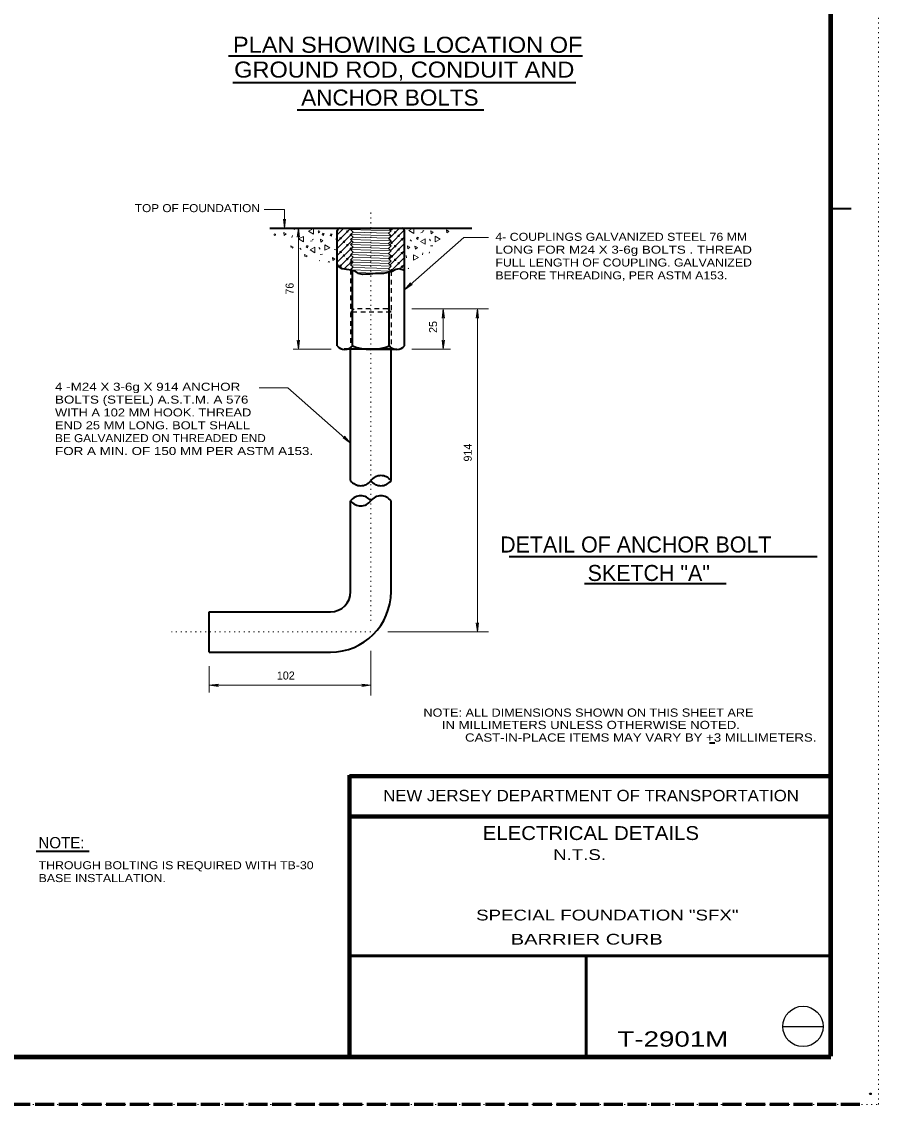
# Model space of a CAD drawing. Extents: x 312583 to 312854, y 144419 to 144597.
# Drawn here: x 312772.2 to 312853.5, y 144418.6 to 144521.4 of the extents above; entities that cross this region are included whole.
import ezdxf
from ezdxf.enums import TextEntityAlignment as Align

# ---------------------------------------------------------------- set-up
doc = ezdxf.new("R2010")
doc.units = 0
doc.header["$LTSCALE"] = 0.3
doc.header["$PDMODE"] = 32
doc.header["$PDSIZE"] = 0.15
for name, pattern in [('DOTTED', [1.5, 0.3, -1.2]), ('LONG_DASHED', [7.5, 6, -1.5]), ('SHORT_DASHED', [2.7, 1.5, -1.2])]:
    doc.linetypes.add(name, pattern=pattern)
for name, color, linetype, lineweight in [('1', 7, 'Continuous', 25), ('10', 7, 'Continuous', 25), ('2', 7, 'Continuous', 13), ('62', 7, 'DOTTED', 13), ('63', 7, 'LONG_DASHED', 60)]:
    doc.layers.add(name, color=color, linetype=linetype, lineweight=lineweight)
doc.layers.add('50', color=7, linetype='Continuous')

msp = doc.modelspace()

# ---------------------------------------------------------------- linework, layer by layer
at = {"layer": '1', "lineweight": 158}
for p, q in [((312849, 144423.1446), (312849, 144585.0846)), ((312616.5, 144423.0846), (312849, 144423.0846))]:
    msp.add_line(p, q, dxfattribs=at)
at = {"layer": '1', "linetype": 'DOTTED', "lineweight": 13}
for p, q in [((312805.3246, 144503.2268), (312805.3246, 144464.4028)), ((312805.3246, 144463.4214), (312786.4032, 144463.4214))]:
    msp.add_line(p, q, dxfattribs=at)
at = {"layer": '1', "lineweight": 35}
for p, q in [((312849, 144503.6216), (312850.932, 144503.6216)), ((312837.4764, 144452.901), (312837.9863, 144452.901))]:
    msp.add_line(p, q, dxfattribs=at)
at = {"layer": '1', "lineweight": 40}
for p, q in [((312802.1352, 144490.5691), (312802.1352, 144501.5171)), ((312808.2839, 144501.7548), (312814.9156, 144501.7548)), ((312808.5216, 144490.5691), (312808.5216, 144501.5171)), ((312803.5689, 144490.5691), (312803.5689, 144497.7221)), ((312807.0802, 144490.5691), (312807.0802, 144497.5764)), ((312807.2412, 144490.2548), (312802.8022, 144490.2548)), ((312805.3246, 144490.2548), (312802.8559, 144490.2548)), ((312803.4079, 144477.7888), (312803.4079, 144490.2548)), ((312805.3246, 144490.2548), (312807.8009, 144490.2548)), ((312807.2412, 144477.7888), (312807.2412, 144490.2548)), ((312803.4079, 144467.2548), (312803.4079, 144475.8721)), ((312807.2412, 144467.2548), (312807.2412, 144475.8721)), ((312789.9912, 144465.3381), (312801.4912, 144465.3381)), ((312789.9912, 144461.5048), (312789.9912, 144465.3381)), ((312789.9912, 144461.5048), (312801.4912, 144461.5048))]:
    msp.add_line(p, q, dxfattribs=at)
at = {"layer": '1', "lineweight": 13}
for p, q in [((312803.4079, 144501.6398), (312807.2412, 144501.5018)), ((312803.4079, 144501.1568), (312807.2412, 144501.0264)), ((312803.4079, 144501.1491), (312803.6456, 144500.9114)), ((312803.6302, 144501.3868), (312807.0036, 144501.2718)), ((312803.6456, 144500.9114), (312807.0189, 144500.7888)), ((312807.2412, 144501.0264), (312807.0036, 144500.7811)), ((312803.4079, 144500.6814), (312807.2412, 144500.5434)), ((312803.4079, 144500.6738), (312803.6456, 144500.4284)), ((312803.4079, 144500.6738), (312803.6456, 144500.4284)), ((312803.4079, 144500.1984), (312807.2412, 144500.0681)), ((312803.4079, 144500.1908), (312803.6456, 144499.9531)), ((312803.4079, 144500.1908), (312803.6456, 144499.9531)), ((312803.4079, 144500.1908), (312803.6456, 144499.9531)), ((312803.6456, 144499.9454), (312807.0036, 144499.8304)), ((312807.2412, 144500.5434), (312807.0036, 144500.3058)), ((312807.2412, 144500.5434), (312807.0036, 144500.3058)), ((312807.2412, 144500.0681), (312807.0036, 144499.8228)), ((312807.2412, 144500.0681), (312807.0036, 144499.8228)), ((312807.2412, 144500.0681), (312807.0036, 144499.8228)), ((312803.4079, 144499.7231), (312807.2412, 144499.5851)), ((312803.4079, 144499.7154), (312803.6456, 144499.4701)), ((312803.4079, 144499.7154), (312803.6456, 144499.4701)), ((312803.4079, 144499.7154), (312803.6456, 144499.4701)), ((312803.4079, 144499.7154), (312803.6456, 144499.4701)), ((312803.4079, 144499.2401), (312807.2412, 144499.1021)), ((312803.4079, 144499.2324), (312803.6456, 144498.9948)), ((312803.4079, 144499.2324), (312803.6456, 144498.9948)), ((312803.4079, 144499.2324), (312803.6456, 144498.9948)), ((312803.4079, 144499.2324), (312803.6456, 144498.9948)), ((312803.4079, 144499.2324), (312803.6456, 144498.9948)), ((312803.4079, 144498.7571), (312807.2412, 144498.6268)), ((312803.4079, 144498.7571), (312803.6456, 144498.5118)), ((312803.4079, 144498.7571), (312803.6456, 144498.5118)), ((312803.4079, 144498.7571), (312803.6456, 144498.5118)), ((312803.4079, 144498.7571), (312803.6456, 144498.5118)), ((312803.4079, 144498.7571), (312803.6456, 144498.5118)), ((312803.4079, 144498.7571), (312803.6456, 144498.5118)), ((312803.6456, 144498.9871), (312807.0036, 144498.8721)), ((312807.2412, 144499.5851), (312807.0036, 144499.3474)), ((312807.2412, 144499.5851), (312807.0036, 144499.3474)), ((312807.2412, 144499.5851), (312807.0036, 144499.3474)), ((312807.2412, 144499.5851), (312807.0036, 144499.3474)), ((312807.2412, 144499.1098), (312807.0036, 144498.8644)), ((312807.2412, 144499.1098), (312807.0036, 144498.8644)), ((312807.2412, 144499.1098), (312807.0036, 144498.8644)), ((312807.2412, 144499.1098), (312807.0036, 144498.8644)), ((312807.2412, 144499.1098), (312807.0036, 144498.8644)), ((312803.4079, 144498.2818), (312807.2412, 144498.1438)), ((312803.4079, 144497.7988), (312807.2412, 144497.6684)), ((312803.6456, 144498.5118), (312807.0036, 144498.3891)), ((312803.6456, 144498.0288), (312807.0036, 144497.9138)), ((312807.2412, 144498.6268), (312807.0036, 144498.3891)), ((312807.2412, 144498.6268), (312807.0036, 144498.3891)), ((312807.2412, 144498.6268), (312807.0036, 144498.3891)), ((312807.2412, 144498.6268), (312807.0036, 144498.3891)), ((312807.2412, 144498.6268), (312807.0036, 144498.3891)), ((312807.2412, 144498.6268), (312807.0036, 144498.3891)), ((312804.0136, 144497.5381), (312806.4899, 144497.4538))]:
    msp.add_line(p, q, dxfattribs=at)
at = {"layer": '1', "linetype": 'SHORT_DASHED'}
for p, q in [((312803.4079, 144497.7988), (312803.4079, 144490.2548)), ((312807.2412, 144497.6684), (312807.2412, 144490.2548)), ((312803.7299, 144494.0881), (312803.4079, 144493.7661)), ((312807.2412, 144493.7661), (312803.4079, 144493.7661)), ((312806.9269, 144494.0881), (312803.7299, 144494.0881)), ((312807.2412, 144493.7661), (312806.9269, 144494.0881))]:
    msp.add_line(p, q, dxfattribs=at)
at = {"layer": '1', "lineweight": 80}
for p, q in [((312803.31, 144423.1446), (312803.31, 144449.8146)), ((312803.31, 144449.7246), (312849, 144449.7246)), ((312803.31, 144445.9146), (312849, 144445.9146))]:
    msp.add_line(p, q, dxfattribs=at)
at = {"layer": '1', "lineweight": 53}
for p, q in [((312849, 144432.6666), (312803.31, 144432.6666)), ((312825.7547, 144432.6666), (312825.7547, 144423.1446))]:
    msp.add_line(p, q, dxfattribs=at)
at = {"layer": '1', "lineweight": 40}
for points in [[(312795.7412, 144501.7548), (312802.3729, 144501.7548), (312808.2839, 144501.7548)], [(312808.5216, 144497.7298), (312808.0156, 144497.8831), (312807.7089, 144497.8371), (312807.3639, 144497.6454), (312806.5129, 144497.4461), (312805.7692, 144497.4461), (312805.2709, 144497.3771), (312804.5272, 144497.3618), (312804.1516, 144497.4461), (312803.8296, 144497.6608), (312803.4539, 144497.7528), (312803.0399, 144497.8141), (312802.6029, 144497.9061), (312802.2579, 144498.0978), (312802.1352, 144498.3661)]]:
    msp.add_lwpolyline(points, dxfattribs=at)
at = {"layer": '1', "lineweight": 13}
for points in [[(312803.5306, 144501.7548), (312803.4079, 144501.6321), (312803.6456, 144501.3868)], [(312803.6456, 144501.3868), (312803.4079, 144501.1491), (312803.6456, 144500.9114)], [(312803.6456, 144500.9114), (312803.4079, 144500.6738), (312803.6456, 144500.4284), (312807.0036, 144500.3058)], [(312807.0036, 144501.7394), (312807.2412, 144501.5018), (312807.0036, 144501.2641)], [(312807.0036, 144501.2641), (312807.2412, 144501.0264), (312807.0036, 144500.7811)], [(312807.0036, 144500.7811), (312807.2412, 144500.5434), (312807.0036, 144500.3058)], [(312803.6456, 144500.4284), (312803.4079, 144500.1908), (312803.6456, 144499.9531)], [(312803.6456, 144499.9531), (312803.4079, 144499.7154), (312803.6456, 144499.4701), (312807.0036, 144499.3474)], [(312807.0036, 144500.3058), (312807.2412, 144500.0681), (312807.0036, 144499.8228)], [(312807.0036, 144499.8228), (312807.2412, 144499.5851), (312807.0036, 144499.3474)], [(312803.6456, 144499.4701), (312803.4079, 144499.2324), (312803.6456, 144498.9948)], [(312803.6456, 144498.9948), (312803.4079, 144498.7571), (312803.6456, 144498.5118)], [(312807.0036, 144499.3474), (312807.2412, 144499.1098), (312807.0036, 144498.8644)], [(312807.0036, 144498.8644), (312807.2412, 144498.6268), (312807.0036, 144498.3891)], [(312803.6456, 144498.5118), (312803.4079, 144498.2741), (312803.6456, 144498.0364)], [(312803.6456, 144498.0364), (312803.4079, 144497.7988), (312803.4539, 144497.7528)], [(312807.0036, 144498.3891), (312807.2412, 144498.1514), (312807.0036, 144497.9061)], [(312807.0036, 144497.9061), (312807.2412, 144497.6684), (312807.1722, 144497.5994)]]:
    msp.add_lwpolyline(points, dxfattribs=at)
at = {"layer": '1', "lineweight": 40}
for centre, radius, start, end in [((312802.371, 144501.5113), 0.2396, 90, 180), ((312808.2782, 144501.5113), 0.2396, 0, 90), ((312802.8507, 144491.2176), 0.9679, 222.07502, 317.92498), ((312805.3254, 144495.239), 4.9893, 249.39031, 290.60969), ((312807.8001, 144491.2176), 0.9679, 222.07502, 317.92498), ((312806.2829, 144477.0662), 1.1979, 36.8699, 143.1301), ((312804.3662, 144478.5037), 1.1979, 216.8699, 323.1301), ((312806.2829, 144478.5037), 1.1979, 216.8699, 323.1301), ((312804.3662, 144475.1495), 1.1979, 36.8699, 143.1301), ((312806.2829, 144475.1495), 1.1979, 36.8699, 143.1301), ((312804.3662, 144476.587), 1.1979, 216.8699, 323.1301), ((312801.4912, 144467.2509), 1.9167, 270, 0), ((312801.4912, 144467.2509), 5.75, 270, 0)]:
    msp.add_arc(centre, radius, start, end, dxfattribs=at)
at = {"layer": '1'}
msp.add_point((312852.75, 144419.5846), dxfattribs=at)
at = {"layer": '10'}
msp.add_line((312844.4383, 144425.966), (312848.2793, 144425.966), dxfattribs=at)
msp.add_circle((312846.3494, 144425.9805), 1.9159, dxfattribs=at)
at = {"layer": '2', "lineweight": 40}
for p, q in [((312791.8044, 144518.1129), (312825.4282, 144518.1129)), ((312792.2248, 144515.5676), (312824.7976, 144515.5676)), ((312798.3202, 144512.9762), (312816.0461, 144512.9762)), ((312818.4671, 144470.5744), (312847.6833, 144470.5744)), ((312825.6135, 144468.0214), (312839.0656, 144468.0214))]:
    msp.add_line(p, q, dxfattribs=at)
at = {"layer": '2'}
for p, q in [((312797.0216, 144502.6211), (312797.1289, 144502.3451)), ((312797.1289, 144501.7548), (312797.0216, 144502.6211)), ((312797.2362, 144502.6211), (312797.1289, 144502.3451)), ((312797.1289, 144501.7548), (312797.2362, 144502.6211)), ((312797.8879, 144501.0494), (312797.8112, 144500.8731)), ((312798.4476, 144501.7548), (312798.3402, 144500.8884)), ((312798.3402, 144500.8884), (312798.4476, 144501.1644)), ((312798.4476, 144501.7548), (312798.4476, 144490.2548)), ((312798.4476, 144501.7548), (312798.5549, 144500.8884)), ((312798.5549, 144500.8884), (312798.4476, 144501.1644)), ((312799.8736, 144501.1951), (312799.8736, 144501.6321)), ((312802.1352, 144500.4668), (312803.4232, 144501.7548)), ((312802.1352, 144501.1184), (312802.7716, 144501.7548)), ((312802.1352, 144499.8151), (312803.4386, 144501.1184)), ((312807.0342, 144500.7504), (312808.0309, 144501.7471)), ((312807.1186, 144500.1831), (312808.4986, 144501.5631)), ((312807.1876, 144501.5554), (312807.3792, 144501.7394)), ((312807.2106, 144499.6234), (312808.5216, 144500.9344)), ((312814.1489, 144500.8654), (312808.5216, 144495.9128)), ((312809.3956, 144501.2564), (312809.3956, 144501.7164)), ((312810.0702, 144501.3178), (312810.2159, 144501.3408)), ((312810.2389, 144501.4481), (312810.3692, 144501.5171)), ((312814.1489, 144500.8654), (312816.4872, 144500.8654)), ((312798.5932, 144499.8611), (312798.7006, 144499.7231)), ((312799.5976, 144500.5204), (312799.7432, 144500.5434)), ((312799.7662, 144500.6508), (312799.8966, 144500.7198)), ((312800.4026, 144499.9148), (312800.5252, 144499.7614)), ((312802.0586, 144500.4974), (312802.1276, 144500.5511)), ((312802.1352, 144499.1634), (312803.5229, 144500.5588)), ((312802.1352, 144498.5118), (312803.6072, 144499.9914)), ((312807.0496, 144498.8184), (312808.5216, 144500.2828)), ((312809.0659, 144500.6584), (312809.1732, 144500.5204)), ((312810.8829, 144500.7121), (312810.9979, 144500.5588)), ((312810.9979, 144500.0604), (312811.2049, 144500.0758)), ((312800.5252, 144499.2631), (312800.7322, 144499.2708)), ((312801.8362, 144499.7231), (312802.0049, 144499.6848)), ((312802.3269, 144498.0594), (312803.4539, 144499.1864)), ((312807.1416, 144498.2511), (312808.5216, 144499.6311)), ((312807.2259, 144497.6838), (312808.5216, 144498.9794)), ((312808.6749, 144499.1558), (312808.6979, 144498.9488)), ((312810.2389, 144499.2324), (312810.2619, 144499.4164)), ((312802.7946, 144497.8754), (312803.5382, 144498.6191)), ((312803.3696, 144497.7988), (312803.6226, 144498.0594)), ((312808.0539, 144497.8601), (312808.5216, 144498.3354)), ((312808.5216, 144495.9128), (312809.0966, 144496.5644)), ((312808.5216, 144495.9128), (312809.2422, 144496.4034)), ((312809.0966, 144496.5644), (312808.9662, 144496.3038)), ((312809.2422, 144496.4034), (312808.9662, 144496.3038)), ((312809.2269, 144494.0881), (312816.4872, 144494.0881)), ((312812.2016, 144494.0881), (312812.0942, 144493.2218)), ((312812.2016, 144494.0881), (312812.2016, 144490.2548)), ((312812.2016, 144494.0881), (312812.3089, 144493.2218)), ((312815.4446, 144494.0881), (312815.3372, 144493.2218)), ((312815.4446, 144494.0881), (312815.4446, 144463.4214)), ((312815.4446, 144494.0881), (312815.5519, 144493.2218)), ((312812.0942, 144493.2218), (312812.2016, 144493.4978)), ((312812.3089, 144493.2218), (312812.2016, 144493.4978)), ((312815.3372, 144493.2218), (312815.4446, 144493.4978)), ((312815.5519, 144493.2218), (312815.4446, 144493.4978)), ((312798.3402, 144491.1211), (312798.4476, 144490.8451)), ((312798.4476, 144490.2548), (312798.3402, 144491.1211)), ((312798.5549, 144491.1211), (312798.4476, 144490.8451)), ((312798.4476, 144490.2548), (312798.5549, 144491.1211)), ((312812.0942, 144491.1211), (312812.2016, 144490.8451)), ((312812.2016, 144490.2548), (312812.0942, 144491.1211)), ((312812.3089, 144491.1211), (312812.2016, 144490.8451)), ((312812.2016, 144490.2548), (312812.3089, 144491.1211)), ((312797.9492, 144490.2548), (312801.5526, 144490.2548)), ((312809.2269, 144490.2548), (312812.8916, 144490.2548)), ((312802.6872, 144481.8368), (312802.9632, 144481.7371)), ((312803.4079, 144481.3461), (312802.6872, 144481.8368)), ((312802.8329, 144481.9978), (312802.9632, 144481.7371)), ((312803.4079, 144481.3461), (312802.8329, 144481.9978)), ((312815.3372, 144464.2878), (312815.4446, 144464.0118)), ((312815.4446, 144463.4214), (312815.3372, 144464.2878)), ((312815.5519, 144464.2878), (312815.4446, 144464.0118)), ((312815.4446, 144463.4214), (312815.5519, 144464.2878)), ((312806.9269, 144463.4214), (312816.4872, 144463.4214)), ((312805.3246, 144461.6428), (312805.3246, 144457.3829)), ((312789.9912, 144460.1631), (312789.9912, 144457.6635)), ((312789.9912, 144458.3652), (312790.8576, 144458.4726)), ((312789.9912, 144458.3652), (312805.3246, 144458.3652)), ((312789.9912, 144458.3652), (312790.8576, 144458.2579)), ((312790.8576, 144458.4726), (312790.5816, 144458.3652)), ((312790.8576, 144458.2579), (312790.5816, 144458.3652)), ((312804.4582, 144458.4726), (312804.7342, 144458.3652)), ((312805.3246, 144458.3652), (312804.4582, 144458.4726)), ((312804.4582, 144458.2579), (312804.7342, 144458.3652)), ((312805.3246, 144458.3652), (312804.4582, 144458.2579))]:
    msp.add_line(p, q, dxfattribs=at)
at = {"layer": '2', "lineweight": 35}
msp.add_line((312773.5512, 144442.627), (312778.5958, 144442.627), dxfattribs=at)
at = {"layer": '2'}
for points in [[(312795.1969, 144503.5258), (312797.1289, 144503.5258), (312797.1289, 144501.7548)], [(312797.9722, 144501.7318), (312797.9646, 144501.7088), (312798.0872, 144501.6398), (312798.0872, 144501.7241)], [(312799.7356, 144501.6398), (312799.4059, 144501.4788), (312799.8736, 144501.1951)], [(312802.1276, 144500.7198), (312802.0202, 144500.7811), (312802.0586, 144500.4974)], [(312809.2882, 144501.7164), (312808.9356, 144501.5401), (312809.3956, 144501.2564)], [(312797.8496, 144499.8534), (312797.9646, 144499.9454), (312797.7269, 144500.0834), (312797.7576, 144499.9148)], [(312799.1452, 144499.0178), (312799.2679, 144499.1098), (312799.0302, 144499.2478), (312799.0609, 144499.0714)], [(312810.9366, 144499.4701), (312810.8982, 144499.4854), (312810.8522, 144499.3934)], [(312800.4869, 144498.6651), (312800.4256, 144498.6881), (312800.4179, 144498.6804)], [(312801.3762, 144498.4964), (312801.4146, 144498.5501), (312801.2919, 144498.5884), (312801.2612, 144498.5194)], [(312808.9432, 144497.9291), (312808.8742, 144497.9674), (312808.8896, 144497.8984)], [(312794.7216, 144486.5901), (312797.4586, 144486.5901), (312803.4079, 144481.3461)]]:
    msp.add_lwpolyline(points, dxfattribs=at)
for points in [[(312797.0982, 144501.0571), (312797.2976, 144501.2104), (312797.0599, 144501.3484)], [(312798.9229, 144500.4591), (312798.9229, 144500.9728), (312798.4629, 144500.7428)], [(312800.8396, 144501.1568), (312800.8856, 144501.2411), (312800.7706, 144501.2794), (312800.7092, 144501.1261), (312800.8396, 144501.0494)], [(312801.6062, 144501.1031), (312801.6522, 144501.1874), (312801.5372, 144501.2258), (312801.4759, 144501.0724), (312801.6062, 144501.0034)], [(312809.7942, 144500.7888), (312809.8402, 144500.8731), (312809.7252, 144500.9114), (312809.6639, 144500.7581), (312809.7866, 144500.6814)], [(312811.0516, 144501.2181), (312811.2509, 144501.3638), (312811.0132, 144501.5094)], [(312811.4426, 144500.9804), (312811.4426, 144500.4668), (312811.9102, 144500.6968)], [(312812.5312, 144501.2948), (312812.7306, 144501.4404), (312812.4929, 144501.5861)], [(312799.3216, 144499.9914), (312799.3676, 144500.0758), (312799.2449, 144500.1064), (312799.1912, 144499.9608), (312799.3139, 144499.8841)], [(312800.0192, 144499.4241), (312800.0192, 144499.9378), (312799.5516, 144499.7001)], [(312800.5789, 144500.4208), (312800.7782, 144500.5664), (312800.5406, 144500.7044)], [(312800.9699, 144500.1831), (312800.9699, 144499.6618), (312801.4376, 144499.8994)], [(312808.8359, 144499.7998), (312809.0276, 144499.9454), (312808.7976, 144500.0834)], [(312809.5489, 144499.7614), (312809.7406, 144499.9071), (312809.5029, 144500.0451)], [(312810.4919, 144500.2214), (312810.4919, 144500.7351), (312810.0242, 144500.4974)], [(312801.7212, 144498.6728), (312801.9129, 144498.8184), (312801.6829, 144498.9641)], [(312809.3879, 144499.2324), (312809.3879, 144498.7188), (312809.8556, 144498.9564)]]:
    msp.add_lwpolyline(points, close=True, dxfattribs=at)
for centre, radius in [((312796.2116, 144501.1276), 0.0784), ((312800.4032, 144501.4025), 0.0866)]:
    msp.add_circle(centre, radius, dxfattribs=at)
for p in [(312802.4496, 144500.7888), (312803.1012, 144501.4328), (312803.4309, 144501.1108), (312807.3102, 144501.6781), (312807.6322, 144501.3484), (312807.9619, 144501.0264), (312802.7792, 144500.4591), (312803.1012, 144500.1371), (312803.4309, 144499.8074), (312807.3102, 144500.3748), (312807.6322, 144500.0451), (312807.9619, 144499.7231), (312808.2839, 144500.6968), (312802.4496, 144499.4854), (312802.7792, 144499.1558), (312803.1012, 144498.8338), (312807.3102, 144499.0714), (312807.6322, 144498.7494), (312808.2839, 144499.4011), (312802.4496, 144498.1821), (312803.4309, 144498.5118), (312807.3102, 144497.7681), (312807.9619, 144498.4198), (312808.2839, 144498.0978)]:
    msp.add_point(p, dxfattribs=at)
at = {"layer": '62'}
msp.add_lwpolyline([(312601.2, 144418.5846), (312853.5, 144418.5846), (312853.5, 144596.7846)], dxfattribs=at)
at = {"layer": '63'}
msp.add_line((312851.75, 144418.5846), (312583.526, 144418.5846), dxfattribs=at)

# ---------------------------------------------------------------- texts
at = {"layer": '1'}
for s, width, p in [('NOTE: ALL DIMENSIONS SHOWN ON THIS SHEET ARE', 1.15, (312810.3185, 144455.3762)), ('     IN MILLIMETERS UNLESS OTHERWISE NOTED.', 1.2, (312810.3184, 144454.2062)), ('CAST-IN-PLACE ITEMS MAY VARY BY +3 MILLIMETERS.', 1.2, (312814.2693, 144453.0153))]:
    msp.add_text(s, height=0.78, dxfattribs=dict(at, width=width)).set_placement(p)
at = {"layer": '1', "width": 1.1}
for s, height, p in [('NEW JERSEY DEPARTMENT OF TRANSPORTATION', 1.08, (312826.2285, 144447.3546)), ('ELECTRICAL DETAILS', 1.315, (312826.2109, 144443.676))]:
    msp.add_text(s, height=height, dxfattribs=at).set_placement(p, align=Align.CENTER)
at = {"layer": '2'}
for s, height, width, p in [('PLAN SHOWING LOCATION OF', 1.52, 1.1, (312808.8237, 144518.4002)), ('GROUND ROD, CONDUIT AND', 1.52, 1.1, (312808.4966, 144516.0433)), ('ANCHOR BOLTS', 1.52, 1.05, (312807.1325, 144513.3894)), ('    N.T.S.  ', 1.02, 1.3, (312824.6461, 144441.778)), ('          SPECIAL FOUNDATION "SFX"          ', 1.02, 1.3, (312827.7748, 144436.04)), ('                BARRIER CURB                ', 1.02, 1.4, (312825.8198, 144433.7476))]:
    msp.add_text(s, height=height, dxfattribs=dict(at, width=width)).set_placement(p, align=Align.CENTER)
for s, width, p in [('TOP OF FOUNDATION', 1.1, (312782.9279, 144503.2727)), ('4- COUPLINGS GALVANIZED STEEL 76 MM', 1.15, (312817.1466, 144500.5501)), ('LONG FOR M24 X 3-6g BOLTS . THREAD', 1.25, (312817.1466, 144499.3301)), ('FULL LENGTH OF COUPLING. GALVANIZED', 1.15, (312817.1466, 144498.1101)), ('BEFORE THREADING, PER ASTM A153.', 1.15, (312817.1466, 144496.8901)), ('4 -M24 X 3-6g X 914 ANCHOR', 1.25, (312775.3487, 144486.3197)), ('BOLTS (STEEL) A.S.T.M. A 576', 1.25, (312775.3487, 144485.0997)), ('WITH A 102 MM HOOK. THREAD ', 1.2, (312775.3487, 144483.8797)), ('END 25 MM LONG. BOLT SHALL', 1.2, (312775.3487, 144482.6597)), ('BE GALVANIZED ON THREADED END', 1.1, (312775.3487, 144481.4397)), ('FOR A MIN. OF 150 MM PER ASTM A153.', 1.25, (312775.3487, 144480.2197)), ('THROUGH BOLTING IS REQUIRED WITH TB-30', 1.15, (312773.7896, 144440.901)), ('BASE INSTALLATION.', 1.15, (312773.7896, 144439.681))]:
    msp.add_text(s, height=0.76, dxfattribs=dict(at, width=width)).set_placement(p)
for s, p in [('76', (312797.9933, 144495.4403)), ('25', (312811.6101, 144491.8062)), ('914', (312814.9038, 144479.5992))]:
    msp.add_text(s, height=0.76, rotation=90, dxfattribs=at).set_placement(p)
for s, height, p in [(' DETAIL OF ANCHOR BOLT', 1.52, (312830.1916, 144470.9649)), ('SKETCH "A"', 1.52, (312831.7068, 144468.2626)), ('NOTE:', 1.07, (312775.9575, 144442.8886))]:
    msp.add_text(s, height=height, dxfattribs=at).set_placement(p, align=Align.CENTER)
msp.add_text('102', height=0.76, dxfattribs=at).set_placement((312796.4038, 144458.9072))
at = {"layer": '50', "width": 1.35}
msp.add_text('T-2901M   ', height=1.457, dxfattribs=at).set_placement((312835.0904, 144424.057), align=Align.CENTER)

doc.saveas('drawing.dxf')
